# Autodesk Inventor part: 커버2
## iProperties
Company: 한국ATC센터
Created: 2015-04
Part Number: 커버2
Document SubType Name: Modeling
Designer: KYOUNG IL JANG
Density: 1 g/cm^3
Material: 기본값
Mass: 82.2849 g
Surface Area: 213.51 cm^2
Volume: 82.2849 cm^3
Author: KYOUNG IL JANG
